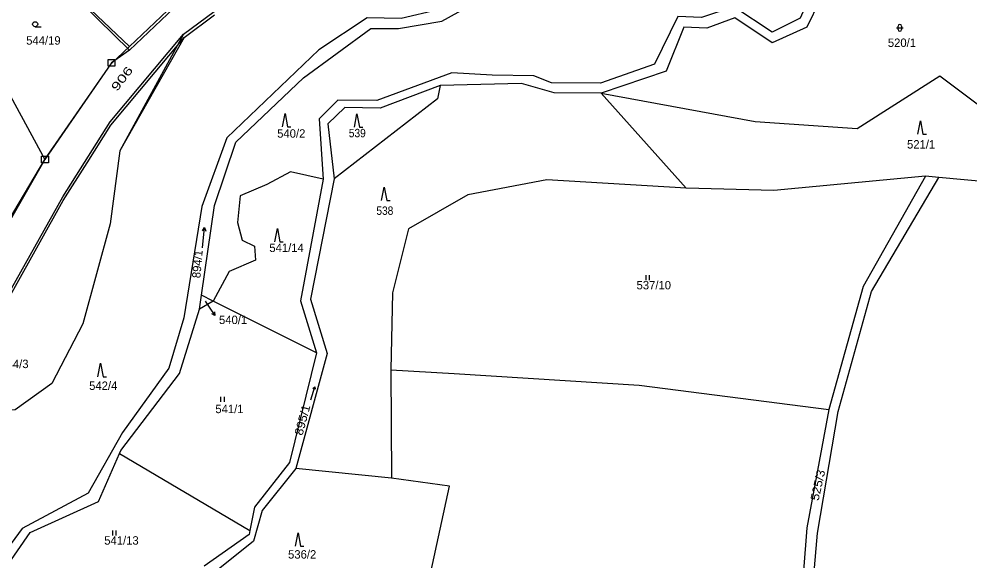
# Model space of a CAD drawing. Extents: x -680102 to -677253, y -1007548 to -1006096.
# Drawn here: x -679441.7 to -679159.4, y -1007197.5 to -1007036.6 of the extents above; entities that cross this region are included whole.
import ezdxf
from ezdxf.enums import TextEntityAlignment as Align

# ---------------------------------------------------------------- set-up
doc = ezdxf.new("R2010")
doc.units = 0
for name, color, linetype, lineweight in [('1', 7, 'Continuous', 25), ('11', 7, 'Continuous', 25), ('16', 7, 'Continuous', 25), ('25', 7, 'Continuous', 25), ('35', 7, 'Continuous', 25)]:
    doc.layers.add(name, color=color, linetype=linetype, lineweight=lineweight)
doc.layers.add('18', color=7, linetype='Continuous')

msp = doc.modelspace()

# ---------------------------------------------------------------- linework, layer by layer
at = {"layer": '1'}
for p, q in [((-679451.09, -1007004.55), (-679408.88, -1007044.79)), ((-679464.13, -1007022.76), (-679434.03, -1007078.35)), ((-679414.32, -1007049.92), (-679408.88, -1007044.79)), ((-679188.64, -1007117.51), (-679168.66, -1007083.66)), ((-679379.32, -1007111.56), (-679384.03, -1007120.38)), ((-679384.03, -1007120.38), (-679388.12, -1007122.76)), ((-679411.85, -1007165.66), (-679373.12, -1007188.44)), ((-679373.36, -1007189.63), (-679386.69, -1007199.1))]:
    msp.add_line(p, q, dxfattribs=at)
for points in [[(-679191.79, -1007012.06), (-679193.5, -1007021.2), (-679203.98, -1007031.12), (-679207.84, -1007039.05), (-679218.17, -1007043.74), (-679229.21, -1007036.25), (-679237.55, -1007039.3), (-679244.37, -1007039.04), (-679249.61, -1007052.13), (-679268.88, -1007058.69), (-679282.87, -1007058.54), (-679292.54, -1007055.79), (-679316.7, -1007056.39), (-679334.5, -1007063.05), (-679344.93, -1007062.85), (-679349.97, -1007067.79), (-679348.09, -1007084.07), (-679355.16, -1007119.77), (-679350.22, -1007135.95), (-679359.5, -1007170.05)], [(-679475.39, -1007165.44), (-679458.72, -1007142.92), (-679428.63, -1007089.4), (-679414.61, -1007067.19), (-679392.8, -1007041.16), (-679383.74, -1007034.41), (-679364.39, -1007022.5), (-679354.81, -1007027.12), (-679350.01, -1007026.23)], [(-679281.81, -1007027.69), (-679288.12, -1007026.06), (-679300.13, -1007025.55), (-679317.23, -1007033.9), (-679328.22, -1007036.44), (-679338.3, -1007036.24), (-679352.63, -1007045.79), (-679380.01, -1007071.86), (-679387.43, -1007092.29), (-679392.71, -1007125.35), (-679397.19, -1007140.32), (-679410.92, -1007159.43), (-679421.1, -1007177.36), (-679440.73, -1007187.9), (-679453.05, -1007204.6)], [(-679408.88, -1007044.79), (-679395.73, -1007032.37), (-679389.08, -1007026.1)], [(-679383.65, -1007091.96), (-679377.34, -1007073.15), (-679357.2, -1007054.13), (-679337.25, -1007039.46), (-679329.01, -1007039.46), (-679316.21, -1007037.24), (-679299.62, -1007028.07), (-679286.9, -1007028.88), (-679282.32, -1007030.74)], [(-679206.61, -1007029.12), (-679209.87, -1007036.35), (-679218.11, -1007040.53), (-679229.51, -1007032.99), (-679239.08, -1007036.15), (-679246.1, -1007035.84), (-679253.01, -1007050.06), (-679269.09, -1007055.66), (-679283.65, -1007055.56), (-679288.84, -1007053.53), (-679301.22, -1007053.32), (-679313.23, -1007052.6), (-679335.42, -1007060.85), (-679347.02, -1007060.75), (-679352.61, -1007066.3), (-679351.39, -1007084.13), (-679358.1, -1007120.25), (-679353.32, -1007135.73), (-679361.36, -1007168.26), (-679371.74, -1007181.5)], [(-679392.8, -1007041.16), (-679411.69, -1007075.81), (-679414.58, -1007097.41), (-679422.73, -1007127.1), (-679431.91, -1007144.79), (-679442.79, -1007152.62), (-679458.6, -1007153.13), (-679464.38, -1007174.57), (-679475.92, -1007196.29)], [(-679460.12, -1007122.3), (-679434.03, -1007078.35), (-679414.32, -1007049.92)], [(-679268.88, -1007058.69), (-679223.22, -1007067.04), (-679192.95, -1007069.15), (-679168.39, -1007053.48), (-679136.21, -1007077.63), (-679096.43, -1007094.76)], [(-679316.7, -1007056.39), (-679317.44, -1007060.33), (-679348.09, -1007084.07)], [(-679172.59, -1007083.3), (-679217.65, -1007087.52), (-679243.69, -1007086.88), (-679268.88, -1007058.69)], [(-679351.39, -1007084.13), (-679361.11, -1007082.02), (-679368.13, -1007085.79), (-679375.97, -1007089.15), (-679376.78, -1007097), (-679375.46, -1007102.29), (-679371.79, -1007104.03), (-679371.49, -1007108.2), (-679379.32, -1007111.56)], [(-679243.69, -1007086.88), (-679284.98, -1007084.34), (-679308.48, -1007088.79), (-679326.05, -1007098.96), (-679330.78, -1007117.89), (-679331.28, -1007140.82), (-679331.07, -1007172.92)], [(-679172.59, -1007083.3), (-679191.11, -1007116.05), (-679201.28, -1007152.6), (-679207.82, -1007187.68), (-679211, -1007228.57)], [(-679145.07, -1007085.84), (-679168.66, -1007083.66), (-679172.59, -1007083.3)], [(-679388.12, -1007122.76), (-679387.52, -1007118.63), (-679383.65, -1007091.96)], [(-679353.32, -1007135.73), (-679384.03, -1007120.38), (-679387.52, -1007118.63)], [(-679207.9, -1007227), (-679204.72, -1007189.29), (-679198.59, -1007153.11), (-679188.64, -1007117.51)], [(-679411.43, -1007164.7), (-679394.03, -1007141.91), (-679388.12, -1007122.76)], [(-679331.28, -1007140.82), (-679312.53, -1007141.88), (-679257.6, -1007145.35), (-679201.28, -1007152.6)], [(-679418.03, -1007179.85), (-679411.85, -1007165.66), (-679411.43, -1007164.7)], [(-679302.96, -1007300.22), (-679312.75, -1007274.71), (-679319.66, -1007271.06), (-679314.77, -1007239.17), (-679310.61, -1007215.32), (-679322.2, -1007213.64), (-679313.91, -1007175.32), (-679331.07, -1007172.92), (-679359.5, -1007170.05), (-679369.48, -1007182.54), (-679372.06, -1007191.61), (-679384.55, -1007201.63), (-679409.35, -1007212.56), (-679417.25, -1007219.13), (-679416.79, -1007226.78)], [(-679455.65, -1007214.04), (-679449.69, -1007205.42), (-679438.39, -1007189.02), (-679418.03, -1007179.85)], [(-679371.74, -1007181.5), (-679373.12, -1007188.44), (-679373.36, -1007189.63)]]:
    msp.add_lwpolyline(points, dxfattribs=at)
at = {"layer": '11'}
for p, q in [((-679392.68, -1007042.12), (-679383.64, -1007035.35)), ((-679414.44, -1007068.19), (-679392.68, -1007042.12)), ((-679392.68, -1007042.12), (-679411.69, -1007075.81))]:
    msp.add_line(p, q, dxfattribs=at)
for points in [[(-679395.73, -1007033.44), (-679408.86, -1007045.89), (-679451.09, -1007004.55)], [(-679433.94, -1007078.32), (-679459.84, -1007123.39), (-679481.69, -1007044.65)], [(-679408.86, -1007045.89), (-679414.17, -1007049.63), (-679433.94, -1007078.32)], [(-679428.52, -1007090.53), (-679421.43, -1007079.32), (-679414.44, -1007068.19)], [(-679474.58, -1007167.77), (-679458.4, -1007144.01), (-679428.52, -1007090.53)]]:
    msp.add_lwpolyline(points, dxfattribs=at)
at = {"layer": '16'}
for p, q in [((-679386.39, -1007120.39), (-679385.17, -1007122.2)), ((-679385.17, -1007122.2), (-679383.497, -1007124.69))]:
    msp.add_line(p, q, dxfattribs=at)
msp.add_lwpolyline([(-679383.64, -1007123.581), (-679383.497, -1007124.69), (-679384.47, -1007124.138)], dxfattribs=at)
at = {"layer": '25'}
for p, q in [((-679436.85, -1007038.92), (-679435.1, -1007038.92)), ((-679181.25, -1007039.24), (-679179.25, -1007039.24)), ((-679180.75, -1007039.74), (-679180.75, -1007038.74)), ((-679179.75, -1007038.74), (-679179.75, -1007039.74)), ((-679387.223, -1007104.512), (-679386.577, -1007098.548)), ((-679255.557, -1007114.155), (-679255.557, -1007112.655)), ((-679254.523, -1007114.155), (-679254.523, -1007112.655)), ((-679355.094, -1007149.656), (-679353.885, -1007145.823)), ((-679381.707, -1007150.285), (-679381.707, -1007148.785)), ((-679380.673, -1007150.285), (-679380.673, -1007148.785)), ((-679413.837, -1007189.945), (-679413.837, -1007188.445)), ((-679412.803, -1007189.945), (-679412.803, -1007188.445))]:
    msp.add_line(p, q, dxfattribs=at)
for points in [[(-679363.45, -1007068.68), (-679362.7, -1007064.68), (-679361.95, -1007068.68), (-679360.95, -1007068.68)], [(-679342.11, -1007068.78), (-679341.36, -1007064.78), (-679340.61, -1007068.78), (-679339.61, -1007068.78)], [(-679174.87, -1007070.84), (-679174.12, -1007066.84), (-679173.37, -1007070.84), (-679172.37, -1007070.84)], [(-679334.03, -1007090.52), (-679333.28, -1007086.52), (-679332.53, -1007090.52), (-679331.53, -1007090.52)], [(-679387.181, -1007099.488), (-679386.577, -1007098.548), (-679386.187, -1007099.596)], [(-679365.71, -1007102.82), (-679364.96, -1007098.82), (-679364.21, -1007102.82), (-679363.21, -1007102.82)], [(-679418.22, -1007142.82), (-679417.47, -1007138.82), (-679416.72, -1007142.82), (-679415.72, -1007142.82)], [(-679354.406, -1007146.361), (-679353.885, -1007145.823), (-679353.767, -1007146.562)], [(-679359.58, -1007193.16), (-679358.83, -1007189.16), (-679358.08, -1007193.16), (-679357.08, -1007193.16)]]:
    msp.add_lwpolyline(points, dxfattribs=at)
msp.add_circle((-679436.85, -1007038.17), 0.75, dxfattribs=at)
for centre, start, end in [((-679180.25, -1007038.74), 0.101, 180.00143), ((-679180.25, -1007039.74), 180.10243, 0.00286)]:
    msp.add_arc(centre, 0.5, start, end, dxfattribs=at)
at = {"layer": '35'}
for points in [[(-679415.17, -1007048.63), (-679413.17, -1007048.63), (-679413.17, -1007050.63), (-679415.17, -1007050.63)], [(-679434.94, -1007077.32), (-679432.94, -1007077.32), (-679432.94, -1007079.32), (-679434.94, -1007079.32)]]:
    msp.add_lwpolyline(points, close=True, dxfattribs=at)

# ---------------------------------------------------------------- texts
at = {"layer": '16'}
msp.add_text('540/1', height=2.5, dxfattribs=at).set_placement((-679382.3, -1007127.19))
at = {"layer": '18'}
for s, height, p in [('544/19', 2.5, (-679439.53, -1007044.24)), ('540/2', 2.5, (-679365.04, -1007071.86)), ('541/14', 2.5, (-679367.36, -1007105.8)), ('537/10', 2.5, (-679258.38, -1007116.89)), ('540/1', 0.1, (-679386.19, -1007120.19)), ('544/3', 2.5, (-679447.19, -1007140.26)), ('541/1', 2.5, (-679383.38, -1007153.63)), ('541/13', 2.5, (-679416.36, -1007192.68))]:
    msp.add_text(s, height=height, dxfattribs=at).set_placement(p)
for s, p in [('520/1', (-679179.62, -1007044.92)), ('521/1', (-679173.919, -1007075.08)), ('542/4', (-679416.66, -1007146.74)), ('536/2', (-679357.62, -1007196.82))]:
    msp.add_text(s, height=2.5, dxfattribs=at).set_placement(p, align=Align.CENTER)
for s, rotation, width, p in [('906', 52.4, 1.45, (-679412.576, -1007058.29)), ('895/1', 75.001, 1.1, (-679357.541, -1007160.436)), ('525/3', 77.301, 1.1, (-679204.371, -1007179.771))]:
    msp.add_text(s, height=2.5, rotation=rotation, dxfattribs=dict(at, width=width)).set_placement(p)
at = {"layer": '18', "width": 0.9}
for s, p in [('539', (-679341.26, -1007071.74)), ('538', (-679333.079, -1007094.77))]:
    msp.add_text(s, height=2.5, dxfattribs=at).set_placement(p, align=Align.CENTER)
at = {"layer": '18'}
msp.add_text('894/1', height=2.5, rotation=85.101, dxfattribs=at).set_placement((-679387.477, -1007109.485), align=Align.CENTER)

doc.saveas('drawing.dxf')
